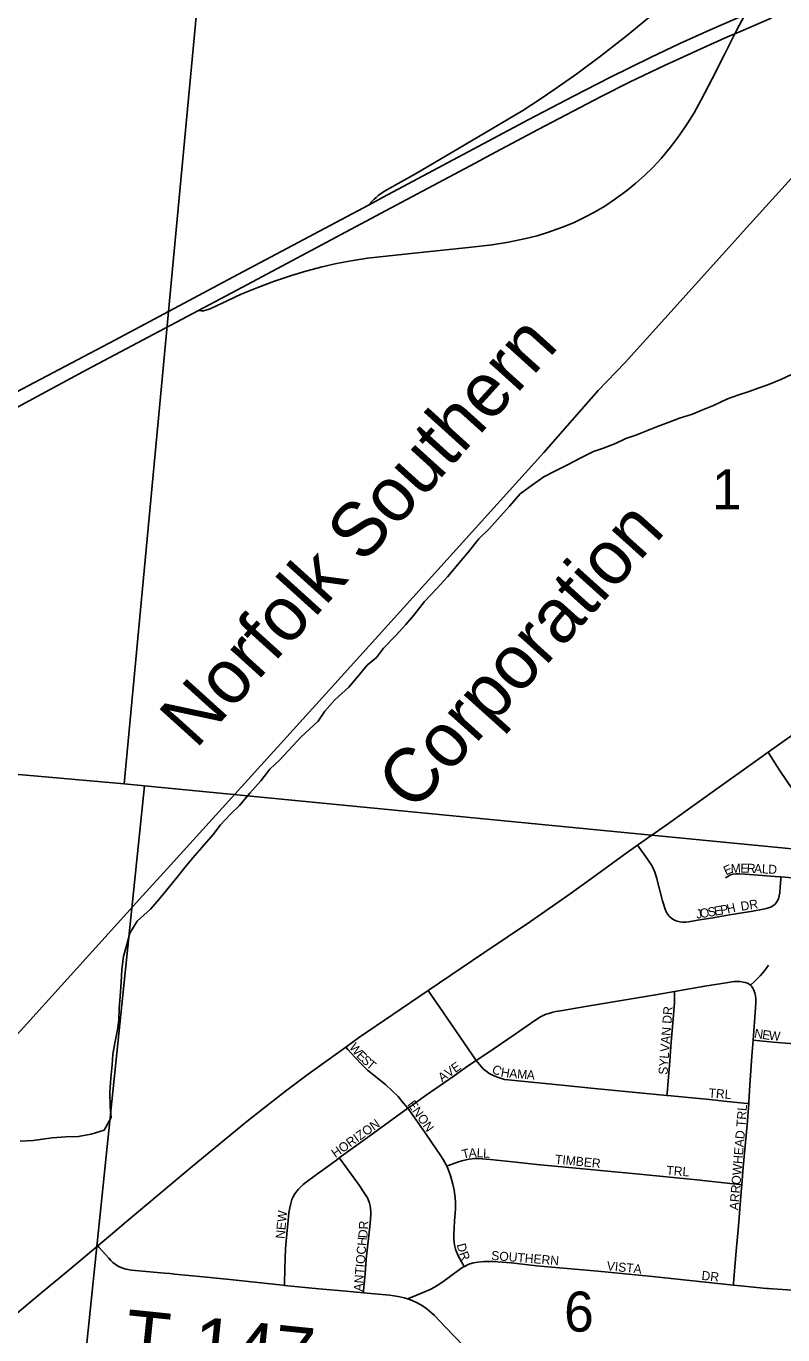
# Model space of a CAD drawing. Extents: x 1410790 to 1770854, y 566777 to 831614.
# Drawn here: x 1559190 to 1563372, y 682819 to 690045 of the extents above; entities that cross this region are included whole.
import ezdxf

# ---------------------------------------------------------------- set-up
doc = ezdxf.new("R2010")
doc.units = 0
for name, color, linetype in [('GM_X_County_Road', 7, 'Continuous'), ('GM_X_Interchange_Ramps', 7, 'Continuous'), ('GM_X_Interstate_Route', 7, 'Continuous'), ('GM_X_Minor_River', 7, 'Continuous'), ('GM_X_Rail_Line', 7, 'Continuous'), ('GM_X_Rail_Line_Text', 7, 'Continuous'), ('GM_X_Section', 7, 'Continuous'), ('GM_X_Section_Text', 7, 'Continuous'), ('GM_X_State_Route', 7, 'Continuous'), ('GM_X_Township_Road', 7, 'Continuous'), ('GM_X_Township_Road_Text', 7, 'Continuous'), ('GM_X_Township_Subdivision', 7, 'Continuous'), ('GM_X_Township_Subdivision_Text', 7, 'Continuous')]:
    doc.layers.add(name, color=color, linetype=linetype)

msp = doc.modelspace()

# ---------------------------------------------------------------- linework, layer by layer
at = {"layer": 'GM_X_County_Road'}
for points in [[(1563291.5, 686035.9), (1563379.9, 686098.6), (1563520.9, 686198.6)], [(1562569, 685521.8), (1562739.3, 685642.1), (1562846, 685718.3), (1563032.9, 685851.4), (1563206.2, 685975.4), (1563291.5, 686035.9)], [(1561412.3, 684720.1), (1561719.4, 684927.2), (1561977.2, 685101.9), (1562197.4, 685254.6), (1562342.6, 685359.4), (1562498.4, 685472), (1562569, 685521.8)], [(1560956.1, 684407.2), (1561027.4, 684458.6), (1561217.1, 684587.5), (1561406.9, 684716.4), (1561412.3, 684720.1)], [(1559585.8, 683309.9), (1559656.5, 683368.8), (1559743.5, 683441.8), (1560106.9, 683748.2), (1560409.4, 683996), (1560505.1, 684071.5), (1560630.2, 684169.1), (1560748.3, 684257.4), (1560885.7, 684356.4), (1560956.1, 684407.2)], [(1558590, 682473.2), (1558689.1, 682556.6), (1558927.1, 682757.4), (1559164.4, 682959.1), (1559267.5, 683045.5), (1559425.3, 683176.1), (1559585.8, 683309.9)]]:
    msp.add_lwpolyline(points, dxfattribs=at)
at = {"layer": 'GM_X_Interchange_Ramps'}
msp.add_lwpolyline([(1563772.3, 691225), (1563636.8, 691079.2), (1563403.4, 690826.8), (1563257.5, 690671.9), (1563142.4, 690555.4), (1563036.4, 690453), (1562904, 690331), (1562769.4, 690211.4), (1562619.9, 690083.9), (1562505.9, 689990.5), (1562364, 689879.8), (1562232.8, 689781.7), (1562112.7, 689696.4), (1562031.2, 689641.5), (1561934.4, 689580.2), (1561723.9, 689453.7), (1561342.4, 689230.4), (1561182.6, 689141.2), (1561159.7, 689127.2), (1561136.2, 689109.9), (1561124.2, 689099.8), (1561112.8, 689089.6), (1561102.1, 689078.4), (1561082.2, 689057.1)], dxfattribs=at)
at = {"layer": 'GM_X_Interstate_Route'}
for points in [[(1559027.9, 687968), (1559680.8, 688311.6), (1560332.4, 688658.3), (1561082.2, 689057.1), (1561186.8, 689112.7), (1561968.5, 689529.3), (1562215.3, 689658.9), (1562419.5, 689763.5), (1562640.2, 689871.9), (1562803.4, 689948.6), (1562982.5, 690029.7), (1563161.5, 690108.4)], [(1563067, 689985.3), (1563107.6, 690003.2), (1563140.8, 690017.9), (1563307, 690088.5), (1563309.4, 690089.5)], [(1562778.3, 689855.7), (1562915.7, 689918.4), (1563067, 689985.3)], [(1561698.5, 689302.8), (1561729.4, 689319.2), (1562019, 689473.6), (1562367.4, 689657), (1562529, 689737.9), (1562721.6, 689829.8), (1562778.3, 689855.7)], [(1560441.3, 688633.1), (1561121.1, 688996), (1561698.5, 689302.8)], [(1560143.2, 688474.6), (1560296.3, 688555.7), (1560441.3, 688633.1)], [(1558809.6, 687766.2), (1559137.8, 687939.3), (1559528.1, 688148.7), (1560143.2, 688474.6)]]:
    msp.add_lwpolyline(points, dxfattribs=at)
at = {"layer": 'GM_X_Minor_River'}
for points in [[(1560804.2, 686206.5), (1560841.1, 686262), (1560896, 686325.5), (1560973.1, 686394.8), (1561032.1, 686464.2), (1561074.8, 686515.8), (1561125.5, 686559.3), (1561164.3, 686610.9), (1561233.3, 686680.3), (1561288.2, 686741.8), (1561333, 686793.3), (1561392.1, 686868.8), (1561457.1, 686938.2), (1561518.1, 687003.6), (1561575.1, 687073.1), (1561634.1, 687142.5), (1561691.2, 687214), (1561748, 687267.4), (1561794.8, 687321), (1561861.9, 687394.4), (1561920.9, 687461.8), (1561987.7, 687513.1), (1562050.4, 687556.5), (1562108.9, 687585.8), (1562185.6, 687625), (1562252.3, 687660.3), (1562324.9, 687695.5), (1562375.3, 687712.9), (1562447.8, 687740.1), (1562504.3, 687767.4), (1562558.7, 687786.8), (1562679.6, 687833.5), (1562738.1, 687856.8), (1562800.5, 687880.1), (1562873, 687903.3), (1562923.4, 687924.7), (1562987.9, 687950), (1563066.6, 687987.1), (1563129.1, 688008.4), (1563185.5, 688027.7), (1563235.8, 688045.2), (1563288.2, 688064.5), (1563360.8, 688093.7), (1563419.3, 688121.1)], [(1559669.6, 684369.1), (1559680.3, 684429), (1559695.2, 684502.9), (1559701.8, 684556.8), (1559704.6, 684622.8), (1559709.4, 684686.8), (1559714.4, 684766.7), (1559719.3, 684836.7), (1559728.1, 684908.6), (1559746.9, 684974.4), (1559763.6, 685036.2), (1559804.4, 685103.7), (1559877, 685168.8), (1559925.6, 685224.2), (1559968.2, 685275.7), (1560024.9, 685345.1), (1560067.5, 685398.5), (1560112, 685452), (1560162.7, 685511.4), (1560223.4, 685580.7), (1560264, 685634.2), (1560318.6, 685693.5), (1560369.1, 685740.9), (1560425.8, 685810.2), (1560486.5, 685877.5), (1560537.2, 685942.9), (1560591.7, 685994.2), (1560709.1, 686120.8), (1560804.2, 686206.5)], [(1559156.7, 683887.3), (1559228.6, 683892.4), (1559280.6, 683899.8), (1559334.6, 683907.1), (1559408.5, 683912.2), (1559478.3, 683913.3), (1559548.4, 683926.5), (1559620.5, 683949.6), (1559659.3, 684019.2), (1559654, 684077.2), (1559653, 684159.3), (1559657.9, 684235.2), (1559664.8, 684309.2), (1559669.6, 684369.1)]]:
    msp.add_lwpolyline(points, dxfattribs=at)
at = {"layer": 'GM_X_Rail_Line'}
msp.add_lwpolyline([(1558017, 683236.3), (1559833.7, 685242.4), (1559988.5, 685412.8), (1560844.3, 686356.1), (1562050.6, 687691.2), (1562351.5, 688032.9), (1562501.2, 688188.4), (1562718.9, 688430.9), (1563206.8, 688970.8), (1563705.8, 689520.6), (1564032, 689882.1), (1564352.5, 690234.9), (1564450.1, 690336.6), (1564655.1, 690537.5), (1564793.1, 690674.4), (1565019.5, 690849.3), (1565156.2, 690953.6), (1565374.8, 691108.1), (1565692.3, 691324.7), (1565844.7, 691432.7), (1565991.3, 691547.7), (1566085.6, 691625.5), (1566311.5, 691821.2), (1566461.5, 691939.2)], dxfattribs=at)
at = {"layer": 'GM_X_Section'}
for points in [[(1555012.2, 691680.4), (1560235.6, 691235.5), (1559732.3, 685861.3), (1554543, 686319.4)], [(1560235.6, 691235.5), (1565558.1, 690607), (1565032.7, 685345.6), (1559844.1, 685849.6), (1559732.3, 685861.3)], [(1559732.3, 685861.3), (1559844.1, 685849.6), (1559303.8, 680639.6), (1554101.5, 681159.8), (1554543, 686319.4)], [(1559844.1, 685849.6), (1565032.7, 685345.6), (1565148.5, 685333.7), (1564673.5, 680210.6), (1559303.8, 680639.6)]]:
    msp.add_lwpolyline(points, close=True, dxfattribs=at)
at = {"layer": 'GM_X_State_Route'}
for points in [[(1563051.3, 689891.8), (1563107.6, 690003.2), (1563114.9, 690017.6), (1563161.5, 690108.4)], [(1562761.6, 689390.9), (1562800.7, 689442.9), (1562846.9, 689510.4), (1562881.4, 689566), (1562921.5, 689637.3), (1562981.7, 689753.9), (1563051.3, 689891.8)], [(1560143.2, 688474.6), (1560157.2, 688473.5), (1560169.7, 688473.9), (1560182.5, 688476.1), (1560196.4, 688480.1), (1560210.2, 688485.2), (1560303.9, 688530.6), (1560378.9, 688564.3), (1560470.2, 688601.7), (1560562.5, 688636.4), (1560656, 688667.8), (1560734.8, 688691.2), (1560825.1, 688716), (1560904.6, 688733.6), (1560986.3, 688749.6), (1561077.2, 688764.1), (1561334.5, 688791.6), (1561634.7, 688823.7), (1561765.2, 688838.2), (1561855.3, 688851.8), (1561951.5, 688871.9), (1562015, 688887.8), (1562077.5, 688906.8), (1562154.5, 688934.6), (1562214.9, 688959.7), (1562274, 688987.6), (1562331.7, 689018.4), (1562387.8, 689051.9), (1562442.4, 689088), (1562508.4, 689136.3), (1562559.3, 689177.3), (1562608.2, 689220.8), (1562654.8, 689266.6), (1562699.1, 689314.7), (1562751.5, 689377.5), (1562761.6, 689390.9)]]:
    msp.add_lwpolyline(points, dxfattribs=at)
at = {"layer": 'GM_X_Township_Road'}
for points in [[(1559585.8, 683309.9), (1559591.5, 683303.4), (1559646.3, 683242), (1559657.3, 683230), (1559669.1, 683218.8), (1559681.8, 683208.7), (1559695.2, 683200), (1559709.5, 683192.5), (1559724.5, 683186.5), (1559740, 683182), (1559772.1, 683176.6), (1559954.1, 683159.5), (1559984.2, 683156.8)], [(1559984.2, 683156.8), (1560000.9, 683155.3), (1560010.6, 683154.3)], [(1560010.6, 683154.3), (1560168.3, 683139), (1560315.3, 683123.8), (1560609.1, 683092.7), (1560617.6, 683091.9)], [(1560617.6, 683091.9), (1560807.9, 683073.4), (1560958.8, 683059.9), (1561053.8, 683051.1)], [(1561053.8, 683051.1), (1561115.5, 683045.4), (1561197.4, 683037.4), (1561246.4, 683030.2), (1561278.8, 683023.2), (1561297.8, 683017.2)], [(1561297.8, 683017.2), (1561314.3, 683011.4), (1561343.4, 682999.6), (1561374.7, 682982.9), (1561404.8, 682962.4), (1561446.8, 682925.8), (1561506.5, 682863.6), (1561608.7, 682756.7)]]:
    msp.add_lwpolyline(points, dxfattribs=at)
at = {"layer": 'GM_X_Township_Subdivision'}
for points in [[(1563661.7, 685320.9), (1563663.3, 685340.7), (1563666.4, 685390), (1563667.4, 685439.5), (1563666, 685456.3), (1563662.9, 685472.9), (1563658.1, 685489), (1563651.8, 685504.7), (1563644.2, 685519.6), (1563618, 685561.6), (1563427.4, 685828), (1563354.4, 685936.5), (1563306.4, 686012.3), (1563291.5, 686035.9)], [(1562569, 685521.8), (1562578.1, 685509.1), (1562624.5, 685444.9), (1562631.4, 685434.7), (1562643.6, 685415.8), (1562651.2, 685402.6), (1562664.6, 685373), (1562673.2, 685343.3), (1562706.3, 685215.7), (1562721, 685169), (1562727.1, 685153.9), (1562735.6, 685140.1), (1562746.5, 685128), (1562759.1, 685117.6), (1562773, 685109.1), (1562788, 685102.8), (1562803.9, 685098.9), (1562820.1, 685097.4), (1562836.4, 685098), (1562852.6, 685099.8), (1562900.8, 685108.3), (1562949.2, 685115.9), (1562997, 685123.5), (1563077.5, 685138), (1563206.3, 685158.9), (1563254.3, 685168), (1563282.5, 685173.6), (1563298.2, 685178), (1563309.2, 685182.7), (1563317.2, 685187.1), (1563328.1, 685195.8), (1563334.8, 685203.7), (1563339.4, 685210.5), (1563347.2, 685225.3), (1563351.4, 685243.5), (1563354.7, 685259.5), (1563357.6, 685291.9), (1563360.7, 685334.7), (1563361.5, 685347.2)], [(1563055.1, 685342), (1563068.2, 685350.4), (1563079, 685356.8), (1563088.6, 685360.5), (1563096.8, 685363.3), (1563114.5, 685364.8), (1563131, 685364.7), (1563164.1, 685363.1), (1563329, 685349.8), (1563361.5, 685347.2)], [(1563361.5, 685347.2), (1563444.8, 685340.3), (1563560.8, 685329.4), (1563645.8, 685322.1), (1563661.7, 685320.9)], [(1563193.4, 684749.4), (1563214.6, 684769.7), (1563245.8, 684801.1), (1563259.3, 684815.6), (1563270, 684829.3), (1563279.2, 684841.7), (1563291.9, 684859.7)], [(1562773.8, 684714.2), (1562940.3, 684743.3), (1563069.6, 684765), (1563102.2, 684769.1), (1563118.8, 684770), (1563135.5, 684769.7), (1563152.4, 684766.8), (1563163.5, 684764), (1563176, 684759.9), (1563185.2, 684755), (1563193.4, 684749.4)], [(1561412.3, 684720.1), (1561423.7, 684703.7), (1561473, 684632.5), (1561677.3, 684333)], [(1561677.3, 684333), (1561730.7, 684368.8), (1561892.6, 684479.5), (1562000.6, 684553.5), (1562033, 684574.2), (1562050.5, 684583.2), (1562064, 684588.7), (1562078.5, 684593.7), (1562101.6, 684600.3), (1562116.6, 684603.3), (1562132.1, 684606.8), (1562292.3, 684633.1), (1562668.4, 684695.9), (1562773.8, 684714.2)], [(1562731.5, 684140.3), (1562732.5, 684151.1), (1562738.8, 684220.9), (1562745.9, 684305.6), (1562755.1, 684434.5), (1562771.3, 684627.7), (1562772.7, 684655.4), (1562774.1, 684685.7), (1562773.8, 684714.2)], [(1563193.4, 684749.4), (1563198.8, 684743.5), (1563206, 684732.7), (1563210.1, 684724.8), (1563213.1, 684716.3), (1563216.3, 684707.3), (1563220.4, 684690.4), (1563222.6, 684673.4), (1563223.2, 684656.3), (1563221.2, 684622.6), (1563207.4, 684445.3)], [(1561299.3, 684069.7), (1561274.5, 684100.4), (1561245.2, 684135), (1561211.7, 684168), (1561175.4, 684201.2), (1561076.7, 684280.5), (1561040.8, 684314.5), (1561005.6, 684351), (1560967.1, 684394.8), (1560956.1, 684407.2)], [(1563183.7, 684095.7), (1563184.3, 684102.8), (1563190, 684196.7), (1563200.3, 684358.2), (1563207.4, 684445.3)], [(1563207.4, 684445.3), (1563319.4, 684434.5), (1563482.7, 684422), (1563579.1, 684415.2)], [(1561299.3, 684069.7), (1561327.6, 684089.6), (1561395.1, 684138.5), (1561554.9, 684249.5), (1561635.6, 684305.3), (1561677.3, 684333)], [(1561677.3, 684333), (1561694.6, 684311.7), (1561704.6, 684300.3), (1561718, 684286.2), (1561724.7, 684280.1), (1561737.2, 684270.3), (1561748.6, 684262.5), (1561764.3, 684253.8), (1561779.6, 684247.2), (1561794.8, 684240.9), (1561816.4, 684233.8), (1561834, 684229.5), (1561853.3, 684226.4), (1561890.7, 684222.8), (1562151.4, 684197.8), (1562330.5, 684179.3), (1562731.5, 684140.3)], [(1562731.5, 684140.3), (1562754.3, 684138.2), (1562966.2, 684118), (1563063.9, 684108), (1563174, 684096.8), (1563183.7, 684095.7)], [(1560920.7, 683795.5), (1561076.1, 683908.7), (1561129.1, 683946.7), (1561299.3, 684069.7)], [(1561514.7, 683750.8), (1561511.5, 683757.6), (1561494.5, 683786.4), (1561478.2, 683812.5), (1561458.6, 683841.8), (1561394.6, 683933.2), (1561330, 684025.9), (1561299.3, 684069.7)], [(1563144.8, 683646.9), (1563153.5, 683744.8), (1563174.3, 683978.5), (1563183.7, 684095.7)], [(1560617.6, 683091.9), (1560617.9, 683102.8), (1560619.8, 683182.6), (1560621, 683242.2), (1560624, 683294.3), (1560631.6, 683376.7), (1560639.7, 683468.6), (1560642.4, 683494.9), (1560646.7, 683519.1), (1560652, 683544.1), (1560657.9, 683565.2), (1560665.8, 683581.6), (1560675.3, 683597.5), (1560685.6, 683611.6), (1560695.6, 683623.6), (1560709.9, 683637.6), (1560721.7, 683648.8), (1560737.1, 683662), (1560787.4, 683698.8), (1560904.5, 683783.7), (1560920.7, 683795.5)], [(1561053.8, 683051.1), (1561054.7, 683060.9), (1561063.3, 683155.1), (1561069.7, 683237.3), (1561091.3, 683433.6), (1561094.7, 683482.6), (1561094.9, 683498.2), (1561093.8, 683514.9), (1561091.5, 683530.7), (1561087.7, 683546.1), (1561082.3, 683561.2), (1561075.6, 683575.7), (1561058.8, 683603.5), (1561031.3, 683644.2), (1560926.4, 683787.7), (1560920.7, 683795.5)], [(1561514.7, 683750.8), (1561524.4, 683754.2), (1561574.1, 683771.5), (1561598.3, 683778.8), (1561621.7, 683785.2), (1561638.1, 683788.8), (1561654.7, 683791), (1561669.8, 683792.5), (1561688.2, 683791.5), (1561753.9, 683786), (1561896.6, 683771.5), (1562012.7, 683759.4), (1562189.3, 683742.3), (1562578.9, 683706), (1562897.4, 683674), (1563098.1, 683652.6), (1563133, 683648.3), (1563144.8, 683646.9)], [(1561611.2, 683195.5), (1561603.6, 683208.6), (1561578.8, 683251.1), (1561567.6, 683277.2), (1561563.1, 683292.2), (1561557.9, 683314.4), (1561553.9, 683347), (1561553.3, 683373.1), (1561557.2, 683446.9), (1561562.4, 683514.2), (1561563.1, 683551.4), (1561561.1, 683575.5), (1561555.9, 683616.6), (1561548.7, 683649.9), (1561537, 683691.1), (1561529.8, 683713.2), (1561521.3, 683736.8), (1561514.7, 683750.8)], [(1563099.1, 683093.2), (1563100.1, 683104.4), (1563113, 683260.3), (1563126.2, 683421.4), (1563143.4, 683631.2), (1563144.8, 683646.9)], [(1561297.8, 683017.2), (1561322.2, 683027.3), (1561387.4, 683054), (1561422.6, 683069.7), (1561446.9, 683082.6), (1561461.9, 683091.1), (1561492.4, 683111.3), (1561585, 683179.2), (1561598.8, 683188.6), (1561611.2, 683195.5)], [(1561611.2, 683195.5), (1561613.6, 683196.8), (1561629, 683205.4), (1561642.1, 683209.9), (1561662.3, 683216.4), (1561686.5, 683220.4), (1561721.1, 683224.3), (1561770.7, 683223.6), (1561869.9, 683215.8), (1562010.9, 683200.1), (1562349.1, 683169.5), (1562652.1, 683140.2), (1563099.1, 683093.2)], [(1563099.1, 683093.2), (1563156, 683087.2), (1563282.6, 683075.2), (1563293.4, 683074.2)], [(1563293.4, 683074.2), (1563315.3, 683072.1), (1563425, 683064.8), (1563467.1, 683062.4)]]:
    msp.add_lwpolyline(points, dxfattribs=at)

# ---------------------------------------------------------------- texts
at = {"layer": 'GM_X_Rail_Line_Text'}
for s, rotation, p in [('Norfolk Southern', 47.90359, (1560127.7, 686048.8)), ('Corporation', 48.01257, (1561330.7, 685698.6))]:
    msp.add_text(s, height=299, rotation=rotation, dxfattribs=at).set_placement(p)
at = {"layer": 'GM_X_Section_Text'}
for s, p in [('1', (1562979.2, 687377.1)), ('6', (1562163, 682836.3))]:
    msp.add_text(s, height=221, rotation=0.00001, dxfattribs=at).set_placement(p)
at = {"layer": 'GM_X_Township_Road_Text'}
msp.add_text('T-147', height=300, rotation=354.13193, dxfattribs=at).set_placement((1559724.1, 682661.3))
at = {"layer": 'GM_X_Township_Subdivision_Text'}
for s, rotation, p in [('E', 24.40213, (1563057.9, 685355.2)), ('M', 2.59677, (1563085.1, 685368.5)), ('E', 359.27599, (1563137.1, 685370.9)), ('R', 357.75259, (1563171.9, 685370.5)), ('A', 357.39843, (1563211.4, 685368.9)), ('L', 357.40364, (1563255.4, 685366.9)), ('D', 357.38751, (1563290.5, 685365.3)), ('P', 9.89496, (1563030.8, 685138.7)), ('H', 11.73501, (1563067.2, 685145.1)), ('DR', 8.97292, (1563142.7, 685159.7)), ('J', 9.70665, (1562896.2, 685115.7)), ('O', 9.70985, (1562917.9, 685119.4)), ('S', 9.71366, (1562961.3, 685126.8)), ('E', 9.70488, (1562996, 685132.7)), ('SYLVAN DR', 85.65797, (1562734.4, 684253.4)), ('N', 351.43249, (1563211.8, 684460)), ('E', 351.44025, (1563255.3, 684453.5)), ('W', 355.00208, (1563293.4, 684447.9)), ('W', 308.57841, (1560972.9, 684405.7)), ('E', 314.60321, (1561012.4, 684356.7)), ('S', 315.68656, (1561037.9, 684330.9)), ('T', 320.13225, (1561066.2, 684303.5)), ('AVE', 35.30743, (1561488.7, 684212)), ('C', 333.31548, (1561759.3, 684268.7)), ('H', 351.04719, (1561810.7, 684245.7)), ('A', 355.41527, (1561858.3, 684238.4)), ('M', 355.59585, (1561902.3, 684234.9)), ('A', 355.60696, (1561955, 684230.8)), ('ENON', 305.71155, (1561295.1, 684091)), ('TRL', 355.59969, (1562960.1, 684130.1)), ('ARROWHEAD TRL', 85.23756, (1563126, 683505.3)), ('HORIZON', 35.44591, (1560899.2, 683794.1)), ('T', 13.16151, (1561604.7, 683790)), ('A', 2.19672, (1561636.4, 683797.6)), ('L', 357.41729, (1561679.3, 683799.3)), ('L', 356.88382, (1561714.3, 683797.8)), ('TIMBER', 354.47201, (1562111, 683764.3)), ('TRL', 355.59969, (1562726.9, 683702.7)), ('NEW', 84.64703, (1560618.1, 683347.3)), ('DR', 86.98901, (1561075.6, 683351.3)), ('ANTIOCH', 85.38971, (1561049.2, 683056.6)), ('D', 283.5459, (1561569.4, 683317.4)), ('R', 290.96314, (1561581.8, 683268)), ('SOUTHERN', 355.42573, (1561759, 683232.6)), ('VISTA', 354.40145, (1562397.1, 683175.4)), ('DR', 353.9889, (1562920.8, 683122.5))]:
    msp.add_text(s, height=50, rotation=rotation, dxfattribs=at).set_placement(p)

doc.saveas('drawing.dxf')
